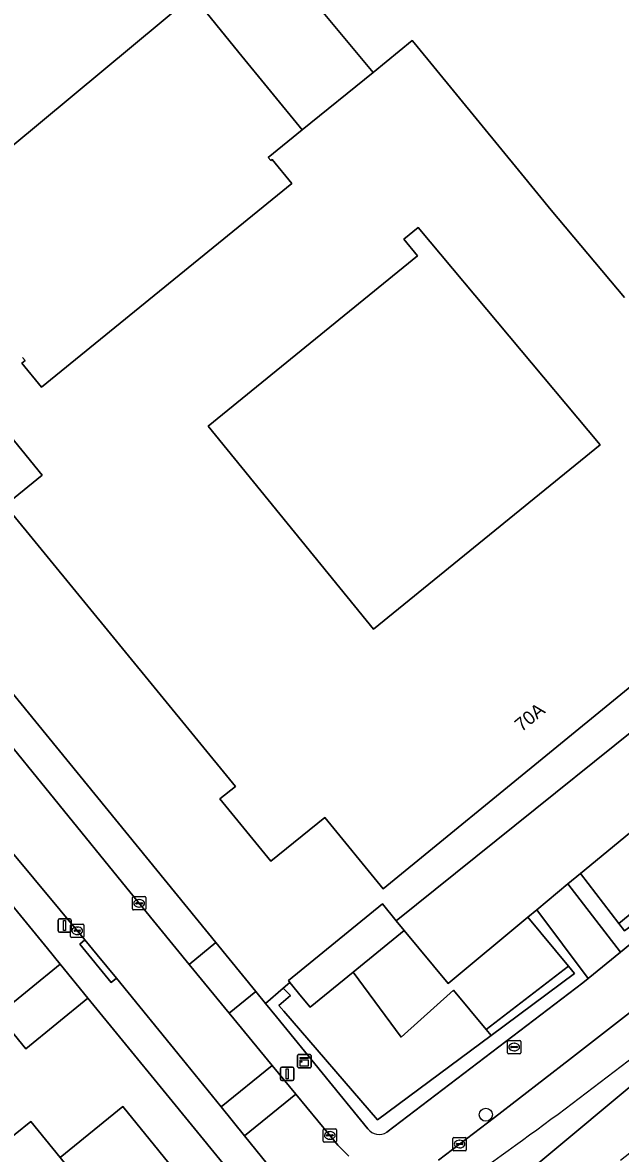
# Model space of a CAD drawing. Extents: x 162073 to 163043, y 381818 to 382561.
# Drawn here: x 162521.9 to 162566.7, y 381872.4 to 381957.1 of the extents above; entities that cross this region are included whole.
import ezdxf

# ---------------------------------------------------------------- set-up
doc = ezdxf.new("R2010")
doc.units = 0
for name, color, linetype in [('IMGEO_Berm_groen', 7, 'Continuous'), ('IMGEO_Boom', 7, 'Continuous'), ('IMGEO_Brandkraan', 7, 'Continuous'), ('IMGEO_Erf', 7, 'Continuous'), ('IMGEO_Fietspad_open', 7, 'Continuous'), ('IMGEO_Groenvoorziening', 7, 'Continuous'), ('IMGEO_Kast', 7, 'Continuous'), ('IMGEO_Kolk', 7, 'Continuous'), ('IMGEO_Lichtmast', 7, 'Continuous'), ('IMGEO_Muur', 7, 'Continuous'), ('IMGEO_Pand', 7, 'Continuous'), ('IMGEO_Pand_nummerreeks', 7, 'Continuous'), ('IMGEO_Parkeervlak_open', 7, 'Continuous'), ('IMGEO_Rijbaan_lokaal_open', 7, 'Continuous'), ('IMGEO_Rijbaan_regionaal_gesloten', 7, 'Continuous'), ('IMGEO_Voetpad_open', 7, 'Continuous')]:
    doc.layers.add(name, color=color, linetype=linetype)

msp = doc.modelspace()

# ---------------------------------------------------------------- linework, layer by layer
at = {"layer": 'IMGEO_Berm_groen'}
msp.add_lwpolyline([(162558.423, 381869.924), (162574.535, 381883.393)], dxfattribs=at)
msp.add_arc((162358.675, 382148.923), 340.842, 304.73515, 308.28362, dxfattribs=at)
at = {"layer": 'IMGEO_Boom'}
msp.add_circle((162556.587, 381875.311), 0.489, dxfattribs=at)
at = {"layer": 'IMGEO_Brandkraan'}
for p, q in [((162558.207, 381879.949), (162558.207, 381880.801)), ((162558.282, 381880.875), (162559.134, 381880.875)), ((162558.509, 381880.418), (162558.907, 381880.418)), ((162558.695, 381880.655), (162558.72, 381880.655)), ((162559.208, 381880.801), (162559.208, 381879.949)), ((162559.134, 381879.875), (162558.282, 381879.875)), ((162558.466, 381880.369), (162558.466, 381880.381)), ((162558.904, 381880.332), (162558.506, 381880.332)), ((162558.718, 381880.095), (162558.693, 381880.095)), ((162558.95, 381880.381), (162558.95, 381880.369))]:
    msp.add_line(p, q, dxfattribs=at)
for points in [[(162558.207, 381879.949), (162558.207, 381880.801)], [(162558.282, 381880.875), (162559.134, 381880.875)], [(162559.208, 381880.801), (162559.208, 381879.949)], [(162559.134, 381879.875), (162558.282, 381879.875)]]:
    msp.add_lwpolyline(points, dxfattribs=at)
for centre, radius, start, end in [((162558.284, 381880.799), 0.0765, 91.55205, 178.44795), ((162558.284, 381880.799), 0.0765, 91.55205, 178.44795), ((162558.506, 381880.378), 0.0403, 85.87752, 175.75265), ((162558.911, 381880.38), 0.0386, 1.73085, 96.63898), ((162559.132, 381880.799), 0.0765, 1.55205, 88.44795), ((162559.132, 381880.799), 0.0765, 1.55205, 88.44795), ((162558.284, 381879.951), 0.0765, 181.55205, 268.44795), ((162558.284, 381879.951), 0.0765, 181.55205, 268.44795), ((162558.503, 381880.368), 0.0366, 178.93798, 274.71019), ((162558.907, 381880.375), 0.043, 264.86636, 352.45326), ((162559.132, 381879.951), 0.0765, 271.55205, 358.44795), ((162559.132, 381879.951), 0.0765, 271.55205, 358.44795)]:
    msp.add_arc(centre, radius, start, end, dxfattribs=at)
for centre, major_axis, ratio, start_param, end_param in [((162558.694, 381880.375), (-0.387, 0.002), 0.722429, 4.712389, 7.853982), ((162558.719, 381880.375), (-0.39, 0.002), 0.717154, 1.570796, 4.712389)]:
    msp.add_ellipse(centre, major_axis=major_axis, ratio=ratio, start_param=start_param, end_param=end_param, dxfattribs=at)
at = {"layer": 'IMGEO_Erf'}
for points in [[(162540.919, 381962.03), (162548.165, 381953.339), (162551.085, 381955.732), (162551.227, 381955.558), (162559.253, 381945.742), (162561.474, 381943.025), (162566.975, 381936.477)], [(162521.92, 381932.008), (162522.115, 381931.767), (162521.874, 381931.571), (162523.331, 381929.779), (162542.062, 381945.012), (162540.598, 381946.811), (162540.505, 381946.734), (162540.309, 381946.974), (162542.837, 381949.03), (162538.114, 381954.837), (162534.655, 381959.09), (162507.558, 381936.537)], [(162524.728, 381886.592), (162523.779, 381887.754), (162520.879, 381891.323), (162500, 381916.926), (162479.554, 381941.998), (162475.997, 381945.948)], [(162520.965, 381921.205), (162523.392, 381923.18), (162518.484, 381929.214)], [(162539.02, 381869.082), (162532.43, 381877.157), (162526.815, 381884.036), (162522.167, 381880.242), (162520.08, 381882.798), (162524.728, 381886.592)]]:
    msp.add_lwpolyline(points, dxfattribs=at)
for points in [[(162565.141, 381925.467), (162551.517, 381941.719), (162550.445, 381940.847), (162551.463, 381939.598), (162535.815, 381926.855), (162548.187, 381911.662)], [(162529.436, 381875.913), (162534.803, 381869.278), (162530.092, 381865.467), (162525.381, 381861.657), (162520.015, 381868.29), (162517.823, 381871), (162522.533, 381874.81), (162524.725, 381872.101)]]:
    msp.add_lwpolyline(points, close=True, dxfattribs=at)
at = {"layer": 'IMGEO_Fietspad_open'}
msp.add_lwpolyline([(162569.845, 381881.378), (162583.714, 381892.733), (162583.892, 381892.823), (162582.341, 381894.747), (162576.86, 381890.263), (162568.456, 381883.814), (162562.84, 381879.432), (162557.234, 381875.101), (162553.054, 381871.913)], dxfattribs=at)
msp.add_arc((162358.675, 382148.923), 340.842, 304.73515, 308.28362, dxfattribs=at)
at = {"layer": 'IMGEO_Groenvoorziening'}
for points in [[(162581.419, 381906.889), (162580.746, 381906.338), (162583.204, 381903.333), (162583.809, 381902.594), (162582.807, 381901.775), (162570.702, 381891.869), (162566.957, 381889.076), (162566.538, 381889.622), (162563.661, 381893.372), (162562.723, 381892.601), (162566.652, 381887.481), (162584.933, 381902.47)], [(162582.807, 381901.775), (162583.809, 381902.594), (162583.204, 381903.333), (162582.205, 381902.511), (162566.538, 381889.622), (162566.957, 381889.076), (162570.702, 381891.869)], [(162563.213, 381885.88), (162562.764, 381886.423), (162556.611, 381881.68), (162556.974, 381881.24)], [(162546.665, 381885.98), (162543.452, 381883.352), (162542.804, 381884.144), (162541.931, 381885.211), (162541.422, 381884.794), (162541.967, 381884.233), (162541.104, 381883.493), (162541.467, 381883.07), (162548.47, 381874.915), (162556.974, 381881.24), (162556.611, 381881.68), (162554.162, 381884.644), (162550.246, 381881.111)]]:
    msp.add_lwpolyline(points, close=True, dxfattribs=at)
for points in [[(162560.403, 381890.646), (162559.731, 381890.088), (162562.764, 381886.423), (162563.213, 381885.88), (162556.974, 381881.24), (162548.47, 381874.915), (162541.467, 381883.07), (162541.104, 381883.493), (162541.967, 381884.233), (162541.422, 381884.794), (162540.112, 381883.637), (162540.928, 381882.637), (162547.762, 381874.26)], [(162549.172, 381874.004), (162563.836, 381885.172), (162564.247, 381885.509), (162560.403, 381890.646)]]:
    msp.add_lwpolyline(points, dxfattribs=at)
msp.add_arc((162548.598, 381874.854), 1.026, 215.41039, 304.00853, dxfattribs=at)
at = {"layer": 'IMGEO_Kast'}
for p, q in [((162542.506, 381878.89), (162542.506, 381879.731)), ((162542.506, 381879.731), (162542.506, 381878.89)), ((162542.581, 381879.815), (162543.422, 381879.815)), ((162543.422, 381879.815), (162542.581, 381879.815)), ((162543.506, 381879.74), (162543.506, 381878.899)), ((162543.506, 381878.899), (162543.506, 381879.74)), ((162543.431, 381878.815), (162542.59, 381878.815)), ((162542.59, 381878.815), (162543.431, 381878.815))]:
    msp.add_line(p, q, dxfattribs=at)
for points in [[(162542.701, 381879.605), (162543.301, 381879.605), (162543.301, 381879.52), (162542.701, 381879.52), (162542.701, 381879.605)], [(162542.701, 381879.43), (162543.301, 381879.43), (162543.301, 381878.941), (162542.701, 381878.941), (162542.701, 381879.43)]]:
    msp.add_lwpolyline(points, dxfattribs=at)
msp.add_circle((162542.785, 381879.279), 0.0377, dxfattribs=at)
for centre, start, end in [((162542.584, 381879.737), 92.4484, 184.28452), ((162542.584, 381879.737), 92.4484, 184.28452), ((162543.428, 381879.737), 2.4484, 94.28452), ((162543.428, 381879.737), 2.4484, 94.28452), ((162542.584, 381878.893), 182.4484, 274.28452), ((162542.584, 381878.893), 182.4484, 274.28452), ((162543.428, 381878.893), 272.4484, 4.28452), ((162543.428, 381878.893), 272.4484, 4.28452)]:
    msp.add_arc(centre, 0.0779, start, end, dxfattribs=at)
at = {"layer": 'IMGEO_Kolk'}
for p, q in [((162530.145, 381890.711), (162530.145, 381891.563)), ((162530.22, 381891.637), (162531.072, 381891.637)), ((162530.633, 381891.417), (162530.658, 381891.417)), ((162531.146, 381891.563), (162531.146, 381890.711)), ((162531.072, 381890.637), (162530.22, 381890.637)), ((162530.404, 381891.131), (162530.404, 381891.143)), ((162530.842, 381891.094), (162530.444, 381891.094)), ((162530.447, 381891.18), (162530.845, 381891.18)), ((162530.656, 381890.857), (162530.631, 381890.857)), ((162530.888, 381891.143), (162530.888, 381891.131)), ((162525.514, 381888.656), (162525.514, 381889.508)), ((162525.589, 381889.582), (162526.441, 381889.582)), ((162525.773, 381889.076), (162525.773, 381889.088)), ((162526.211, 381889.039), (162525.813, 381889.039)), ((162525.816, 381889.125), (162526.214, 381889.125)), ((162526.002, 381889.362), (162526.027, 381889.362)), ((162526.257, 381889.088), (162526.257, 381889.076)), ((162526.515, 381889.508), (162526.515, 381888.656)), ((162526.441, 381888.582), (162525.589, 381888.582)), ((162526.025, 381888.802), (162526, 381888.802)), ((162544.414, 381873.335), (162544.414, 381874.187)), ((162544.489, 381874.261), (162545.341, 381874.261)), ((162544.673, 381873.755), (162544.673, 381873.767)), ((162545.111, 381873.718), (162544.713, 381873.718)), ((162544.716, 381873.804), (162545.114, 381873.804)), ((162544.902, 381874.041), (162544.927, 381874.041)), ((162545.157, 381873.767), (162545.157, 381873.755)), ((162545.415, 381874.187), (162545.415, 381873.335)), ((162545.341, 381873.261), (162544.489, 381873.261)), ((162544.925, 381873.481), (162544.9, 381873.481)), ((162554.125, 381872.687), (162554.125, 381873.539)), ((162554.2, 381873.613), (162555.052, 381873.613)), ((162554.384, 381873.107), (162554.384, 381873.119)), ((162554.822, 381873.07), (162554.424, 381873.07)), ((162554.427, 381873.156), (162554.825, 381873.156)), ((162554.636, 381872.833), (162554.611, 381872.833)), ((162554.613, 381873.393), (162554.638, 381873.393)), ((162554.868, 381873.119), (162554.868, 381873.107)), ((162555.126, 381873.539), (162555.126, 381872.687)), ((162555.052, 381872.613), (162554.2, 381872.613))]:
    msp.add_line(p, q, dxfattribs=at)
for points in [[(162530.145, 381890.711), (162530.145, 381891.563)], [(162530.22, 381891.637), (162531.072, 381891.637)], [(162531.146, 381891.563), (162531.146, 381890.711)], [(162531.072, 381890.637), (162530.22, 381890.637)], [(162525.514, 381888.656), (162525.514, 381889.508)], [(162525.589, 381889.582), (162526.441, 381889.582)], [(162526.515, 381889.508), (162526.515, 381888.656)], [(162526.441, 381888.582), (162525.589, 381888.582)], [(162544.414, 381873.335), (162544.414, 381874.187)], [(162544.489, 381874.261), (162545.341, 381874.261)], [(162545.415, 381874.187), (162545.415, 381873.335)], [(162545.341, 381873.261), (162544.489, 381873.261)], [(162554.125, 381872.687), (162554.125, 381873.539)], [(162554.2, 381873.613), (162555.052, 381873.613)], [(162555.126, 381873.539), (162555.126, 381872.687)], [(162555.052, 381872.613), (162554.2, 381872.613)]]:
    msp.add_lwpolyline(points, dxfattribs=at)
for centre, radius, start, end in [((162530.222, 381891.561), 0.0765, 91.55205, 178.44795), ((162530.222, 381891.561), 0.0765, 91.55205, 178.44795), ((162531.07, 381891.561), 0.0765, 1.55205, 88.44795), ((162531.07, 381891.561), 0.0765, 1.55205, 88.44795), ((162530.222, 381890.713), 0.0765, 181.55205, 268.44795), ((162530.222, 381890.713), 0.0765, 181.55205, 268.44795), ((162530.444, 381891.14), 0.0403, 85.87752, 175.75265), ((162530.441, 381891.13), 0.0366, 178.93798, 274.71019), ((162530.845, 381891.137), 0.043, 264.86636, 352.45326), ((162530.849, 381891.142), 0.0386, 1.73085, 96.63898), ((162531.07, 381890.713), 0.0765, 271.55205, 358.44795), ((162531.07, 381890.713), 0.0765, 271.55205, 358.44795), ((162525.591, 381889.506), 0.0765, 91.55205, 178.44795), ((162525.591, 381889.506), 0.0765, 91.55205, 178.44795), ((162525.813, 381889.085), 0.0403, 85.87752, 175.75265), ((162525.81, 381889.075), 0.0366, 178.93798, 274.71019), ((162526.214, 381889.082), 0.043, 264.86636, 352.45326), ((162526.218, 381889.087), 0.0386, 1.73085, 96.63898), ((162526.439, 381889.506), 0.0765, 1.55205, 88.44795), ((162526.439, 381889.506), 0.0765, 1.55205, 88.44795), ((162525.591, 381888.658), 0.0765, 181.55205, 268.44795), ((162525.591, 381888.658), 0.0765, 181.55205, 268.44795), ((162526.439, 381888.658), 0.0765, 271.55205, 358.44795), ((162526.439, 381888.658), 0.0765, 271.55205, 358.44795), ((162544.491, 381874.185), 0.0765, 91.55205, 178.44795), ((162544.491, 381874.185), 0.0765, 91.55205, 178.44795), ((162544.713, 381873.764), 0.0403, 85.87752, 175.75265), ((162544.71, 381873.754), 0.0366, 178.93798, 274.71019), ((162545.114, 381873.761), 0.043, 264.86636, 352.45326), ((162545.118, 381873.766), 0.0386, 1.73085, 96.63898), ((162545.339, 381874.185), 0.0765, 1.55205, 88.44795), ((162545.339, 381874.185), 0.0765, 1.55205, 88.44795), ((162544.491, 381873.337), 0.0765, 181.55205, 268.44795), ((162544.491, 381873.337), 0.0765, 181.55205, 268.44795), ((162545.339, 381873.337), 0.0765, 271.55205, 358.44795), ((162545.339, 381873.337), 0.0765, 271.55205, 358.44795), ((162554.202, 381873.537), 0.0765, 91.55205, 178.44795), ((162554.202, 381873.537), 0.0765, 91.55205, 178.44795), ((162554.424, 381873.116), 0.0403, 85.87752, 175.75265), ((162554.421, 381873.106), 0.0366, 178.93798, 274.71019), ((162554.825, 381873.113), 0.043, 264.86636, 352.45326), ((162554.829, 381873.118), 0.0386, 1.73085, 96.63898), ((162555.05, 381873.537), 0.0765, 1.55205, 88.44795), ((162555.05, 381873.537), 0.0765, 1.55205, 88.44795), ((162554.202, 381872.689), 0.0765, 181.55205, 268.44795), ((162554.202, 381872.689), 0.0765, 181.55205, 268.44795), ((162555.05, 381872.689), 0.0765, 271.55205, 358.44795), ((162555.05, 381872.689), 0.0765, 271.55205, 358.44795)]:
    msp.add_arc(centre, radius, start, end, dxfattribs=at)
for centre, major_axis, ratio, start_param, end_param in [((162530.632, 381891.137), (-0.387, 0.002), 0.722429, 4.712389, 7.853982), ((162530.657, 381891.137), (-0.39, 0.002), 0.717154, 1.570796, 4.712389), ((162526.001, 381889.082), (-0.387, 0.002), 0.722429, 4.712389, 7.853982), ((162526.026, 381889.082), (-0.39, 0.002), 0.717154, 1.570796, 4.712389), ((162544.901, 381873.761), (-0.387, 0.002), 0.722429, 4.712389, 7.853982), ((162544.926, 381873.761), (-0.39, 0.002), 0.717154, 1.570796, 4.712389), ((162554.612, 381873.113), (-0.387, 0.002), 0.722429, 4.712389, 7.853982), ((162554.637, 381873.113), (-0.39, 0.002), 0.717154, 1.570796, 4.712389)]:
    msp.add_ellipse(centre, major_axis=major_axis, ratio=ratio, start_param=start_param, end_param=end_param, dxfattribs=at)
at = {"layer": 'IMGEO_Lichtmast'}
for p, q in [((162524.575, 381889.067), (162524.575, 381889.867)), ((162524.575, 381889.867), (162524.575, 381889.067)), ((162524.675, 381889.967), (162525.465, 381889.967)), ((162525.465, 381889.967), (162524.675, 381889.967)), ((162525.565, 381889.867), (162525.565, 381889.067)), ((162525.565, 381889.067), (162525.565, 381889.867)), ((162525.465, 381888.967), (162524.675, 381888.967)), ((162524.675, 381888.967), (162525.465, 381888.967)), ((162541.226, 381877.969), (162541.226, 381878.769)), ((162541.226, 381878.769), (162541.226, 381877.969)), ((162541.326, 381878.869), (162542.116, 381878.869)), ((162542.116, 381878.869), (162541.326, 381878.869)), ((162542.216, 381878.769), (162542.216, 381877.969)), ((162542.216, 381877.969), (162542.216, 381878.769)), ((162542.116, 381877.869), (162541.326, 381877.869)), ((162541.326, 381877.869), (162542.116, 381877.869))]:
    msp.add_line(p, q, dxfattribs=at)
for points in [[(162524.995, 381889.842), (162525.145, 381889.842), (162525.145, 381889.092), (162524.995, 381889.092), (162524.995, 381889.842)], [(162541.646, 381878.744), (162541.796, 381878.744), (162541.796, 381877.994), (162541.646, 381877.994), (162541.646, 381878.744)]]:
    msp.add_lwpolyline(points, dxfattribs=at)
for centre, start, end in [((162524.675, 381889.867), 90, 180), ((162524.675, 381889.867), 90, 180), ((162525.465, 381889.867), 0, 90), ((162525.465, 381889.867), 360, 90), ((162524.675, 381889.067), 180, 270), ((162524.675, 381889.067), 180, 270), ((162525.465, 381889.067), 270, 0), ((162525.465, 381889.067), 270, 0), ((162541.326, 381878.769), 90, 180), ((162541.326, 381878.769), 90, 180), ((162542.116, 381878.769), 0, 90), ((162542.116, 381878.769), 360, 90), ((162541.326, 381877.969), 180, 270), ((162541.326, 381877.969), 180, 270), ((162542.116, 381877.969), 270, 0), ((162542.116, 381877.969), 270, 0)]:
    msp.add_arc(centre, 0.1, start, end, dxfattribs=at)
at = {"layer": 'IMGEO_Muur'}
for points in [[(162524.728, 381886.592), (162523.779, 381887.754)], [(162526.815, 381884.036), (162532.43, 381877.157)]]:
    msp.add_lwpolyline(points, dxfattribs=at)
at = {"layer": 'IMGEO_Pand'}
for points in [[(162542.837, 381949.03), (162548.165, 381953.339), (162540.919, 381962.03), (162540.007, 381963.125), (162538.067, 381965.451), (162537.565, 381966.054), (162537.29, 381965.824), (162534.514, 381963.506), (162528.039, 381971.287), (162498.859, 381947.001), (162505.384, 381939.152), (162507.558, 381936.537), (162534.655, 381959.09), (162538.114, 381954.837)], [(162565.141, 381925.467), (162548.187, 381911.662), (162535.815, 381926.855), (162551.463, 381939.598), (162550.445, 381940.847), (162551.517, 381941.719)], [(162526.815, 381884.036), (162524.728, 381886.592), (162520.08, 381882.798), (162522.167, 381880.242)], [(162524.725, 381872.101), (162530.092, 381865.467), (162534.803, 381869.278), (162529.436, 381875.913)], [(162524.725, 381872.101), (162522.533, 381874.81), (162517.823, 381871), (162520.015, 381868.29), (162525.381, 381861.657), (162530.092, 381865.467)]]:
    msp.add_lwpolyline(points, close=True, dxfattribs=at)
for points in [[(162566.975, 381936.477), (162561.474, 381943.025), (162559.253, 381945.742), (162551.227, 381955.558), (162551.085, 381955.732), (162548.165, 381953.339), (162542.837, 381949.03), (162540.309, 381946.974), (162540.505, 381946.734), (162540.598, 381946.811), (162542.062, 381945.012), (162523.331, 381929.779), (162521.874, 381931.571), (162522.115, 381931.767), (162521.92, 381932.008)], [(162518.484, 381929.214), (162523.392, 381923.18), (162520.965, 381921.205)], [(162520.5, 381921.098), (162537.847, 381899.893), (162536.692, 381898.947), (162540.51, 381894.28), (162544.533, 381897.571), (162548.915, 381892.214), (162574.906, 381913.476)]]:
    msp.add_lwpolyline(points, dxfattribs=at)
at = {"layer": 'IMGEO_Parkeervlak_open'}
for points in [[(162520.5, 381921.098), (162519.284, 381922.585), (162512.749, 381917.178), (162536.387, 381888.203), (162539.376, 381884.54), (162540.112, 381883.637), (162541.422, 381884.794), (162541.931, 381885.211), (162541.818, 381885.349), (162548.846, 381891.098), (162549.882, 381889.832), (162576.654, 381911.34), (162574.906, 381913.476), (162548.915, 381892.214), (162544.533, 381897.571), (162540.51, 381894.28), (162536.692, 381898.947), (162537.847, 381899.893)], [(162582.205, 381902.511), (162579.219, 381906.16), (162563.661, 381893.372), (162566.538, 381889.622)], [(162562.764, 381886.423), (162559.731, 381890.088), (162553.763, 381885.128), (162550.48, 381889.101), (162546.665, 381885.98), (162550.246, 381881.111), (162554.162, 381884.644), (162556.611, 381881.68)]]:
    msp.add_lwpolyline(points, close=True, dxfattribs=at)
at = {"layer": 'IMGEO_Rijbaan_lokaal_open'}
for points in [[(162503.432, 381916.577), (162506.083, 381913.313), (162516.305, 381900.831), (162520.92, 381895.221), (162526.59, 381888.392), (162527.505, 381887.289), (162528.94, 381885.529), (162533.859, 381879.496), (162536.776, 381875.893), (162540.607, 381878.995), (162537.389, 381882.905), (162534.39, 381886.566), (162529.722, 381892.262), (162519.563, 381904.75), (162514.252, 381911.144), (162513.176, 381912.467), (162508.478, 381918.241), (162507.291, 381919.708)], [(162538.525, 381873.733), (162542.373, 381876.848), (162540.607, 381878.995), (162536.776, 381875.893)]]:
    msp.add_lwpolyline(points, close=True, dxfattribs=at)
for points in [[(162576.654, 381911.34), (162549.882, 381889.832), (162550.48, 381889.101), (162553.763, 381885.128), (162559.731, 381890.088), (162560.403, 381890.646), (162562.723, 381892.601), (162563.661, 381893.372), (162579.219, 381906.16)], [(162546.346, 381872.217), (162546.105, 381872.442), (162545.873, 381872.678), (162545.516, 381873.026), (162544.845, 381873.844), (162542.373, 381876.848), (162538.525, 381873.733), (162540.645, 381871.115)]]:
    msp.add_lwpolyline(points, dxfattribs=at)
at = {"layer": 'IMGEO_Rijbaan_regionaal_gesloten'}
msp.add_lwpolyline([(162566.658, 381871.895), (162569.902, 381874.457), (162573.002, 381876.978), (162576.216, 381879.533), (162579.43, 381882.088), (162582.644, 381884.642), (162585.718, 381887.166), (162588.92, 381889.795), (162590.619, 381891.129), (162591.753, 381893.037), (162591.519, 381892.972), (162584.354, 381892.005), (162579.129, 381887.315), (162574.535, 381883.393), (162558.423, 381869.924)], dxfattribs=at)
at = {"layer": 'IMGEO_Voetpad_open'}
for points in [[(162649.444, 381958.748), (162651.329, 381956.438), (162613.031, 381925.508), (162608.52, 381921.81), (162607.178, 381920.71), (162604.738, 381918.709), (162590.856, 381907.327), (162588.263, 381905.2), (162587.298, 381904.409), (162584.933, 381902.47), (162566.652, 381887.481), (162564.247, 381885.509), (162563.836, 381885.172), (162549.172, 381874.004)], [(162519.563, 381904.75), (162529.722, 381892.262), (162534.39, 381886.566), (162536.387, 381888.203), (162512.749, 381917.178)], [(162553.054, 381871.913), (162557.234, 381875.101), (162562.84, 381879.432), (162568.456, 381883.814), (162576.86, 381890.263), (162582.341, 381894.747), (162587.206, 381898.727), (162586.89, 381899.114), (162589.8, 381901.496), (162590.116, 381901.109), (162593.897, 381904.203), (162606.742, 381914.713)], [(162520.879, 381891.323), (162523.779, 381887.754), (162524.728, 381886.592), (162526.815, 381884.036), (162532.43, 381877.157), (162539.02, 381869.082), (162540.645, 381871.115), (162538.525, 381873.733), (162536.776, 381875.893), (162533.859, 381879.496), (162528.94, 381885.529), (162528.554, 381885.212), (162526.204, 381888.075), (162526.59, 381888.392), (162520.92, 381895.221)], [(162547.762, 381874.26), (162540.928, 381882.637), (162540.112, 381883.637), (162539.376, 381884.54), (162537.389, 381882.905), (162540.607, 381878.995), (162542.373, 381876.848), (162544.845, 381873.844), (162545.516, 381873.026), (162545.873, 381872.678), (162546.105, 381872.442), (162546.346, 381872.217)]]:
    msp.add_lwpolyline(points, dxfattribs=at)
for points in [[(162562.723, 381892.601), (162560.403, 381890.646), (162564.247, 381885.509), (162566.652, 381887.481)], [(162550.48, 381889.101), (162549.882, 381889.832), (162548.846, 381891.098), (162541.818, 381885.349), (162541.931, 381885.211), (162542.804, 381884.144), (162543.452, 381883.352), (162546.665, 381885.98)], [(162528.94, 381885.529), (162527.505, 381887.289), (162526.59, 381888.392), (162526.204, 381888.075), (162528.554, 381885.212)], [(162536.387, 381888.203), (162534.39, 381886.566), (162537.389, 381882.905), (162539.376, 381884.54)]]:
    msp.add_lwpolyline(points, close=True, dxfattribs=at)
msp.add_arc((162548.598, 381874.854), 1.026, 215.41039, 304.00853, dxfattribs=at)

# ---------------------------------------------------------------- texts
at = {"layer": 'IMGEO_Pand_nummerreeks'}
msp.add_text('70A', height=1, rotation=39.28496, dxfattribs=at).set_placement((162559.265, 381903.937))

doc.saveas('drawing.dxf')
